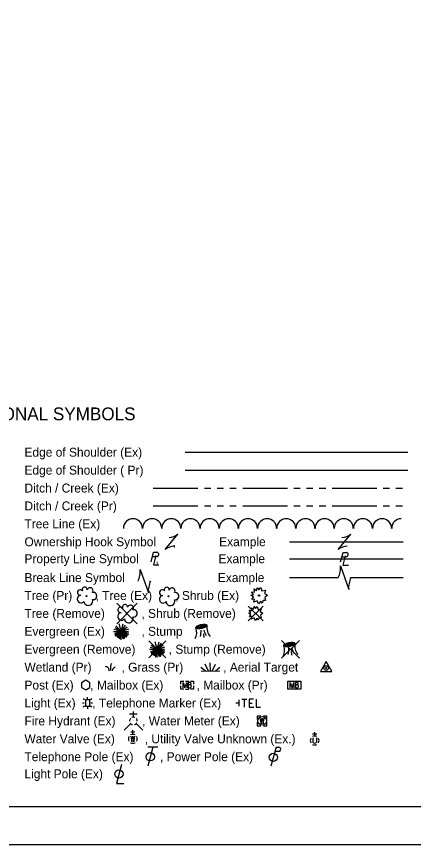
# Model space of a CAD drawing. Extents: x 0 to 34, y 0 to 22.
# Drawn here: x 7.18 to 12.46, y 0 to 11 of the extents above; entities that cross this region are included whole.
import ezdxf

# ---------------------------------------------------------------- set-up
doc = ezdxf.new("R2010")
doc.units = 0
for name, color, linetype in [('SH_Border', 7, 'Continuous'), ('SH_Cut_Line', 7, 'Continuous'), ('SH_Text', 7, 'Continuous')]:
    doc.layers.add(name, color=color, linetype=linetype)

msp = doc.modelspace()

# ---------------------------------------------------------------- linework, layer by layer
at = {"layer": 'SH_Border'}
msp.add_lwpolyline([(1.5, 21.5), (33.5, 21.5), (33.5, 0.5), (1.5, 0.5)], close=True, dxfattribs=at)
at = {"layer": 'SH_Cut_Line'}
msp.add_lwpolyline([(0, 0), (34, 0), (34, 22), (0, 22)], close=True, dxfattribs=at)
at = {"layer": 'SH_Text'}
for p, q in [((9.426, 5.211), (12.387, 5.211)), ((9.426, 4.973), (12.387, 4.973)), ((9.001, 4.735), (9.596, 4.735)), ((9.681, 4.735), (9.766, 4.735)), ((9.851, 4.735), (9.936, 4.735)), ((10.021, 4.735), (10.106, 4.735)), ((10.191, 4.735), (10.786, 4.735)), ((10.871, 4.735), (10.956, 4.735)), ((11.041, 4.735), (11.126, 4.735)), ((11.211, 4.735), (11.296, 4.735)), ((11.381, 4.735), (11.976, 4.735)), ((12.061, 4.735), (12.146, 4.735)), ((12.231, 4.735), (12.316, 4.735)), ((9.001, 4.497), (9.596, 4.497)), ((9.681, 4.497), (9.766, 4.497)), ((9.851, 4.497), (9.936, 4.497)), ((10.021, 4.497), (10.106, 4.497)), ((10.191, 4.497), (10.786, 4.497)), ((10.871, 4.497), (10.956, 4.497)), ((11.041, 4.497), (11.126, 4.497)), ((11.211, 4.497), (11.296, 4.497)), ((11.381, 4.497), (11.976, 4.497)), ((12.061, 4.497), (12.146, 4.497)), ((12.231, 4.497), (12.316, 4.497)), ((9.16, 3.919), (9.33, 4.123)), ((11.462, 3.919), (11.632, 4.123)), ((9.245, 4.021), (9.245, 4.021)), ((10.812, 4.021), (12.327, 4.021)), ((11.547, 4.021), (11.547, 4.021)), ((8.991, 3.825), (9.046, 3.825)), ((9.025, 3.798), (9.025, 3.798)), ((10.812, 3.796), (12.327, 3.796)), ((11.511, 3.821), (11.567, 3.821)), ((11.545, 3.795), (11.545, 3.795)), ((8.827, 3.654), (8.937, 3.341)), ((11.492, 3.702), (11.603, 3.389)), ((10.812, 3.545), (11.462, 3.545)), ((11.547, 3.545), (11.547, 3.545)), ((11.632, 3.545), (12.327, 3.545)), ((8.882, 3.498), (8.882, 3.498)), ((8.515, 3.205), (8.787, 2.933)), ((8.787, 3.205), (8.515, 2.933)), ((10.265, 3.168), (10.462, 2.971)), ((10.462, 3.168), (10.265, 2.971)), ((8.651, 3.069), (8.651, 3.069)), ((10.363, 3.069), (10.363, 3.069)), ((8.575, 2.831), (8.492, 2.88)), ((8.575, 2.831), (8.501, 2.905)), ((8.575, 2.831), (8.549, 2.929)), ((8.575, 2.831), (8.602, 2.931)), ((8.575, 2.831), (8.631, 2.913)), ((8.575, 2.831), (8.653, 2.891)), ((8.575, 2.831), (8.676, 2.865)), ((8.47, 2.831), (8.575, 2.831)), ((8.575, 2.831), (8.481, 2.856)), ((8.575, 2.831), (8.484, 2.798)), ((8.575, 2.831), (8.49, 2.782)), ((8.575, 2.831), (8.492, 2.767)), ((8.575, 2.831), (8.512, 2.757)), ((8.575, 2.831), (8.526, 2.746)), ((8.575, 2.831), (8.54, 2.739)), ((8.575, 2.831), (8.548, 2.728)), ((8.575, 2.831), (8.563, 2.733)), ((8.575, 2.831), (8.671, 2.833)), ((8.575, 2.72), (8.575, 2.831)), ((8.575, 2.831), (8.595, 2.732)), ((8.575, 2.831), (8.616, 2.732)), ((8.575, 2.831), (8.629, 2.75)), ((8.575, 2.831), (8.651, 2.756)), ((8.575, 2.831), (8.656, 2.777)), ((8.575, 2.831), (8.67, 2.79)), ((8.575, 2.831), (8.678, 2.811)), ((9.658, 2.831), (9.658, 2.831)), ((8.941, 2.707), (9.168, 2.479)), ((9.168, 2.707), (8.941, 2.479)), ((9.054, 2.593), (8.971, 2.642)), ((9.054, 2.593), (8.98, 2.667)), ((9.054, 2.593), (9.028, 2.691)), ((9.054, 2.593), (9.081, 2.693)), ((9.054, 2.593), (9.111, 2.676)), ((9.054, 2.593), (9.132, 2.653)), ((10.709, 2.711), (10.945, 2.475)), ((10.945, 2.711), (10.709, 2.475)), ((8.95, 2.593), (9.054, 2.593)), ((9.054, 2.593), (8.961, 2.618)), ((9.054, 2.593), (8.963, 2.56)), ((9.054, 2.593), (8.97, 2.545)), ((9.054, 2.593), (8.971, 2.529)), ((9.054, 2.593), (8.992, 2.519)), ((9.054, 2.593), (9.005, 2.508)), ((9.054, 2.593), (9.019, 2.501)), ((9.054, 2.593), (9.028, 2.49)), ((9.054, 2.593), (9.043, 2.496)), ((9.054, 2.593), (9.155, 2.627)), ((9.054, 2.593), (9.15, 2.595)), ((9.054, 2.482), (9.054, 2.593)), ((9.054, 2.593), (9.074, 2.495)), ((9.054, 2.593), (9.095, 2.494)), ((9.054, 2.593), (9.108, 2.512)), ((9.054, 2.593), (9.131, 2.518)), ((9.054, 2.593), (9.136, 2.539)), ((9.054, 2.593), (9.149, 2.552)), ((9.054, 2.593), (9.157, 2.573)), ((9.054, 2.593), (9.054, 2.593)), ((10.827, 2.593), (10.827, 2.593)), ((10.827, 2.593), (10.827, 2.593)), ((9.694, 2.303), (9.636, 2.352)), ((9.736, 2.304), (9.691, 2.394)), ((9.761, 2.304), (9.76, 2.411)), ((9.787, 2.304), (9.828, 2.396)), ((9.828, 2.305), (9.885, 2.355)), ((9.637, 2.302), (9.885, 2.306)), ((9.431, 2.169), (9.473, 2.169)), ((9.452, 2.117), (9.452, 2.117)), ((10.879, 2.117), (10.879, 2.117)), ((9.431, 2.065), (9.473, 2.065)), ((8.082, 1.879), (8.06, 1.879)), ((8.086, 1.92), (8.07, 1.936)), ((8.127, 1.933), (8.127, 1.956)), ((8.127, 1.879), (8.127, 1.879)), ((8.183, 1.936), (8.168, 1.92)), ((8.194, 1.879), (8.171, 1.879)), ((10.144, 1.879), (10.101, 1.879)), ((10.144, 1.837), (10.144, 1.922)), ((8.086, 1.838), (8.07, 1.822)), ((8.127, 1.825), (8.127, 1.802)), ((8.183, 1.822), (8.168, 1.838)), ((8.737, 1.692), (8.737, 1.765)), ((8.788, 1.729), (8.686, 1.729)), ((8.701, 1.605), (8.613, 1.517)), ((8.737, 1.641), (8.737, 1.641)), ((8.737, 1.641), (8.737, 1.641)), ((8.773, 1.605), (8.861, 1.517)), ((10.449, 1.641), (10.449, 1.641)), ((8.756, 1.49), (8.702, 1.49)), ((8.729, 1.463), (8.729, 1.517)), ((11.176, 1.467), (11.122, 1.467)), ((11.149, 1.44), (11.149, 1.494)), ((8.729, 1.403), (8.729, 1.403)), ((11.126, 1.417), (11.126, 1.359)), ((11.149, 1.381), (11.149, 1.381)), ((11.172, 1.417), (11.172, 1.359)), ((9.063, 1.293), (8.927, 1.293)), ((8.995, 1.293), (8.927, 1.038)), ((10.635, 1.293), (10.567, 1.038)), ((10.621, 1.238), (10.671, 1.238)), ((10.635, 1.293), (10.671, 1.293))]:
    msp.add_line(p, q, dxfattribs=at)
for points in [[(8.973, 3.757), (9.006, 3.883), (9.05, 3.883)], [(11.494, 3.754), (11.527, 3.88), (11.571, 3.88)], [(9.036, 3.839), (9.002, 3.713), (9.077, 3.713)], [(11.557, 3.836), (11.523, 3.71), (11.597, 3.71)], [(10.405, 3.384), (10.431, 3.415), (10.448, 3.37), (10.495, 3.378), (10.48, 3.335), (10.52, 3.31), (10.484, 3.279), (10.495, 3.24), (10.463, 3.243), (10.449, 3.204), (10.431, 3.233), (10.402, 3.199), (10.384, 3.236), (10.34, 3.218), (10.348, 3.258), (10.314, 3.254), (10.334, 3.288), (10.301, 3.312), (10.333, 3.323), (10.307, 3.358), (10.347, 3.353), (10.345, 3.397), (10.377, 3.373), (10.386, 3.415), (10.405, 3.384)], [(10.36, 3.134), (10.382, 3.161), (10.397, 3.123), (10.437, 3.129), (10.424, 3.093), (10.459, 3.071), (10.428, 3.045), (10.437, 3.012), (10.409, 3.014), (10.398, 2.981), (10.382, 3.006), (10.358, 2.977), (10.342, 3.009), (10.305, 2.993), (10.312, 3.027), (10.283, 3.024), (10.3, 3.053), (10.272, 3.073), (10.299, 3.083), (10.277, 3.112), (10.311, 3.108), (10.31, 3.145), (10.337, 3.125), (10.344, 3.161), (10.36, 3.134)], [(8.048, 2.085), (8.103, 2.053), (8.158, 2.085), (8.158, 2.149), (8.103, 2.181), (8.048, 2.149), (8.048, 2.085)], [(9.367, 2.128), (9.367, 2.169), (9.409, 2.169)], [(9.409, 2.065), (9.367, 2.065), (9.367, 2.106)], [(9.397, 2.083), (9.397, 2.151), (9.422, 2.083), (9.446, 2.151), (9.446, 2.083)], [(9.496, 2.12), (9.499, 2.123), (9.5, 2.124), (9.501, 2.126), (9.502, 2.127), (9.503, 2.129), (9.503, 2.131), (9.504, 2.134), (9.504, 2.136), (9.504, 2.138), (9.504, 2.141), (9.503, 2.144), (9.501, 2.146), (9.499, 2.148), (9.496, 2.149), (9.495, 2.15), (9.493, 2.151), (9.466, 2.151), (9.466, 2.083), (9.496, 2.083), (9.5, 2.085), (9.503, 2.088), (9.506, 2.092), (9.507, 2.097), (9.508, 2.102), (9.508, 2.105), (9.507, 2.108), (9.504, 2.113), (9.502, 2.116), (9.496, 2.12), (9.466, 2.12)], [(9.495, 2.169), (9.537, 2.169), (9.537, 2.128)], [(9.537, 2.106), (9.537, 2.065), (9.495, 2.065)], [(10.824, 2.083), (10.824, 2.151), (10.848, 2.083), (10.872, 2.151), (10.872, 2.083)], [(10.922, 2.12), (10.925, 2.123), (10.927, 2.124), (10.928, 2.126), (10.928, 2.127), (10.929, 2.129), (10.93, 2.131), (10.931, 2.134), (10.931, 2.136), (10.931, 2.138), (10.93, 2.141), (10.929, 2.144), (10.928, 2.146), (10.925, 2.148), (10.923, 2.149), (10.922, 2.15), (10.919, 2.151), (10.893, 2.151), (10.893, 2.083), (10.922, 2.083), (10.926, 2.085), (10.929, 2.088), (10.932, 2.092), (10.934, 2.097), (10.934, 2.102), (10.934, 2.105), (10.933, 2.108), (10.931, 2.113), (10.928, 2.116), (10.922, 2.12), (10.893, 2.12)], [(10.178, 1.932), (10.244, 1.932)], [(10.212, 1.932), (10.212, 1.826)], [(10.335, 1.932), (10.278, 1.932), (10.278, 1.826), (10.34, 1.826)], [(10.278, 1.879), (10.319, 1.879)], [(10.369, 1.932), (10.369, 1.826), (10.427, 1.826)], [(10.432, 1.705), (10.385, 1.705), (10.385, 1.658)], [(10.42, 1.679), (10.435, 1.603), (10.449, 1.679), (10.463, 1.603), (10.477, 1.679)], [(10.512, 1.658), (10.512, 1.705), (10.466, 1.705)], [(10.385, 1.624), (10.385, 1.577), (10.432, 1.577)], [(10.466, 1.577), (10.512, 1.577), (10.512, 1.624)], [(8.702, 1.438), (8.716, 1.365), (8.729, 1.438), (8.743, 1.365), (8.756, 1.438)], [(8.577, 1.062), (8.51, 0.808), (8.61, 0.808)]]:
    msp.add_lwpolyline(points, dxfattribs=at)
for points in [[(11.226, 2.296), (11.379, 2.296), (11.302, 2.432)], [(10.794, 2.169), (10.964, 2.169), (10.964, 2.065), (10.794, 2.065)], [(8.098, 1.837), (8.155, 1.837), (8.155, 1.922), (8.098, 1.922)]]:
    msp.add_lwpolyline(points, close=True, dxfattribs=at)
for centre, radius in [((8.113, 3.3), 0.00714), ((9.205, 3.297), 0.00612), ((10.408, 3.307), 0.00979), ((8.651, 3.069), 0.00612), ((10.363, 3.069), 0.00832), ((11.302, 2.345), 0.0298), ((11.302, 2.345), 0.0068), ((10.449, 1.641), 0.0574), ((8.961, 1.165), 0.0553), ((10.599, 1.157), 0.0553), ((8.543, 0.936), 0.0553)]:
    msp.add_circle(centre, radius, dxfattribs=at)
for centre, radius, start, end in [((8.731, 4.2), 0.127, 0.0098, 179.9926), ((8.986, 4.2), 0.127, 0.0098, 179.9926), ((9.241, 4.2), 0.127, 0.0098, 179.9926), ((9.496, 4.2), 0.127, 0.0098, 179.9926), ((9.751, 4.2), 0.127, 0.0098, 179.9926), ((10.006, 4.2), 0.127, 0.0098, 179.9926), ((10.261, 4.2), 0.127, 0.0098, 179.9926), ((10.516, 4.2), 0.127, 0.0098, 179.9926), ((10.771, 4.2), 0.127, 0.0098, 179.9926), ((11.026, 4.2), 0.127, 0.0098, 179.9926), ((11.281, 4.2), 0.127, 0.0098, 179.9926), ((11.536, 4.2), 0.127, 0.0098, 179.9926), ((11.791, 4.2), 0.127, 0.0098, 179.9926), ((12.046, 4.2), 0.127, 0.0098, 179.9926), ((12.301, 4.2), 0.127, 89.9955, 179.9926), ((9.196, 4.306), 0.227, 273.6945, 306.337), ((11.498, 4.306), 0.227, 273.6945, 306.337), ((9.295, 3.736), 0.227, 93.6945, 126.337), ((11.597, 3.736), 0.227, 93.6945, 126.337), ((9.045, 3.854), 0.0293, 270.471, 81.3281), ((11.566, 3.851), 0.0293, 270.471, 81.3281), ((8.545, 3.627), 0.284, 332.9422, 5.5848), ((11.21, 3.674), 0.284, 332.9422, 5.5848), ((11.885, 3.416), 0.284, 152.9422, 185.5848), ((8.088, 3.386), 0.0336, 354.0047, 205.9741), ((8.16, 3.372), 0.0396, 323.83, 165.0376), ((9.219, 3.369), 0.284, 152.9422, 185.5848), ((9.18, 3.383), 0.0336, 354.0047, 205.9741), ((8.04, 3.261), 0.0503, 96.1722, 320.5737), ((8.029, 3.348), 0.0375, 39.0625, 279.5412), ((8.201, 3.301), 0.0488, 259.1453, 101.4596), ((9.132, 3.258), 0.0503, 96.1722, 320.5737), ((9.121, 3.345), 0.0375, 39.0625, 279.5412), ((9.251, 3.369), 0.0396, 323.83, 165.0376), ((9.293, 3.298), 0.0488, 259.1453, 101.4596), ((8.137, 3.234), 0.0582, 184.9476, 19.4572), ((9.229, 3.231), 0.0582, 184.9476, 19.4572), ((8.567, 3.117), 0.0375, 39.0625, 279.5412), ((8.626, 3.155), 0.0336, 354.0047, 205.9741), ((8.698, 3.141), 0.0396, 323.83, 165.0376), ((8.739, 3.07), 0.0488, 259.1453, 101.4596), ((8.578, 3.03), 0.0503, 96.1722, 320.5737), ((8.675, 3.003), 0.0582, 184.9476, 19.4572), ((9.41, 2.816), 0.17, 331.5338, 20.9269), ((9.896, 2.88), 0.182, 171.4106, 219.9194), ((9.423, 2.832), 0.215, 340.7938, 3.5481), ((9.824, 2.797), 0.155, 178.7926, 197.1224), ((9.934, 2.918), 0.269, 194.9653, 212.1216), ((11.065, 2.642), 0.182, 171.4106, 219.9194), ((10.579, 2.578), 0.17, 331.5338, 20.9269), ((10.592, 2.594), 0.215, 340.7938, 3.5481), ((10.993, 2.559), 0.155, 178.7926, 197.1224), ((11.103, 2.68), 0.269, 194.9653, 212.1216), ((8.737, 1.641), 0.051, 140.021, 184.0629), ((8.737, 1.641), 0.051, 68.1395, 112.038), ((8.737, 1.641), 0.051, 356.0165, 39.9889), ((8.737, 1.641), 0.051, 211.8788, 255.8479), ((8.737, 1.641), 0.051, 283.8239, 329.9097), ((8.729, 1.403), 0.0595, 150.0184, 209.9816), ((8.729, 1.403), 0.0595, 60.0184, 120.0157), ((8.729, 1.403), 0.0595, 330.0184, 29.9816), ((11.149, 1.381), 0.0595, 60.0184, 120.0157), ((8.729, 1.403), 0.0595, 239.9843, 299.9816), ((11.149, 1.381), 0.0595, 150.0184, 209.9816), ((11.149, 1.381), 0.0595, 239.9843, 299.9816), ((11.149, 1.37), 0.0255, 205.1924, 334.8076), ((11.149, 1.381), 0.0595, 330.0184, 29.9816), ((10.672, 1.265), 0.0271, 268.8767, 91.1233)]:
    msp.add_arc(centre, radius, start, end, dxfattribs=at)
for centre, major_axis in [((9.642, 2.895), (0.0738, 0.0159)), ((9.642, 2.895), (0.0553, 0.012)), ((9.642, 2.895), (0.0415, 0.009)), ((9.642, 2.895), (0.0233, 0.005)), ((9.642, 2.895), (0.0131, 0.0028)), ((10.811, 2.657), (0.0738, 0.0159)), ((10.811, 2.657), (0.0553, 0.012)), ((10.811, 2.657), (0.0415, 0.009)), ((10.811, 2.657), (0.0233, 0.005)), ((10.811, 2.657), (0.0131, 0.0028))]:
    msp.add_ellipse(centre, major_axis=major_axis, ratio=0.36865, dxfattribs=at)
for points in [[(8.361, 2.368), (8.397, 2.353), (8.412, 2.308)], [(8.436, 2.311), (8.436, 2.352), (8.441, 2.389), (8.448, 2.407)], [(8.459, 2.305), (8.469, 2.338), (8.494, 2.358)]]:
    msp.add_spline(points, degree=3, dxfattribs=at)

# ---------------------------------------------------------------- texts
for s, height, p in [('CONVENTIONAL SYMBOLS', 0.17, (5.809, 5.636)), ('Edge of Shoulder (Ex)', 0.119, (7.287, 5.152)), ('Edge of Shoulder ( Pr)', 0.119, (7.287, 4.914)), ('Ditch / Creek (Ex)', 0.119, (7.287, 4.676)), ('Ditch / Creek (Pr)', 0.119, (7.287, 4.438)), ('Tree Line (Ex)', 0.119, (7.287, 4.2)), ('Ownership Hook Symbol     ,             Example', 0.119, (7.287, 3.962)), ('Property Line Symbol     ,                  Example', 0.119, (7.287, 3.737)), ('Break Line Symbol       ,                    Example', 0.119, (7.287, 3.486)), ('Tree (Pr)       , Tree (Ex)       , Shrub (Ex)', 0.119, (7.287, 3.248)), ('Tree (Remove)           , Shrub (Remove)', 0.119, (7.287, 3.01)), ('Evergreen (Ex)           , Stump ', 0.119, (7.287, 2.772)), ('Evergreen (Remove)          , Stump (Remove)', 0.119, (7.287, 2.534)), ('Wetland (Pr)         , Grass (Pr)            , Aerial Target    ', 0.119, (7.287, 2.296)), ('Post (Ex)     , Mailbox (Ex)          , Mailbox (Pr)', 0.119, (7.287, 2.058)), ('Light (Ex)     , Telephone Marker (Ex)     ', 0.119, (7.287, 1.82)), ('Fire Hydrant (Ex)        , Water Meter (Ex)', 0.119, (7.287, 1.582)), ('Water Valve (Ex)         , Utility Valve Unknown (Ex.)', 0.119, (7.287, 1.344)), ('Telephone Pole (Ex)        , Power Pole (Ex)', 0.119, (7.287, 1.106)), ('Light Pole (Ex)     ', 0.119, (7.287, 0.879))]:
    msp.add_text(s, height=height, dxfattribs=at).set_placement(p)

doc.saveas('drawing.dxf')
